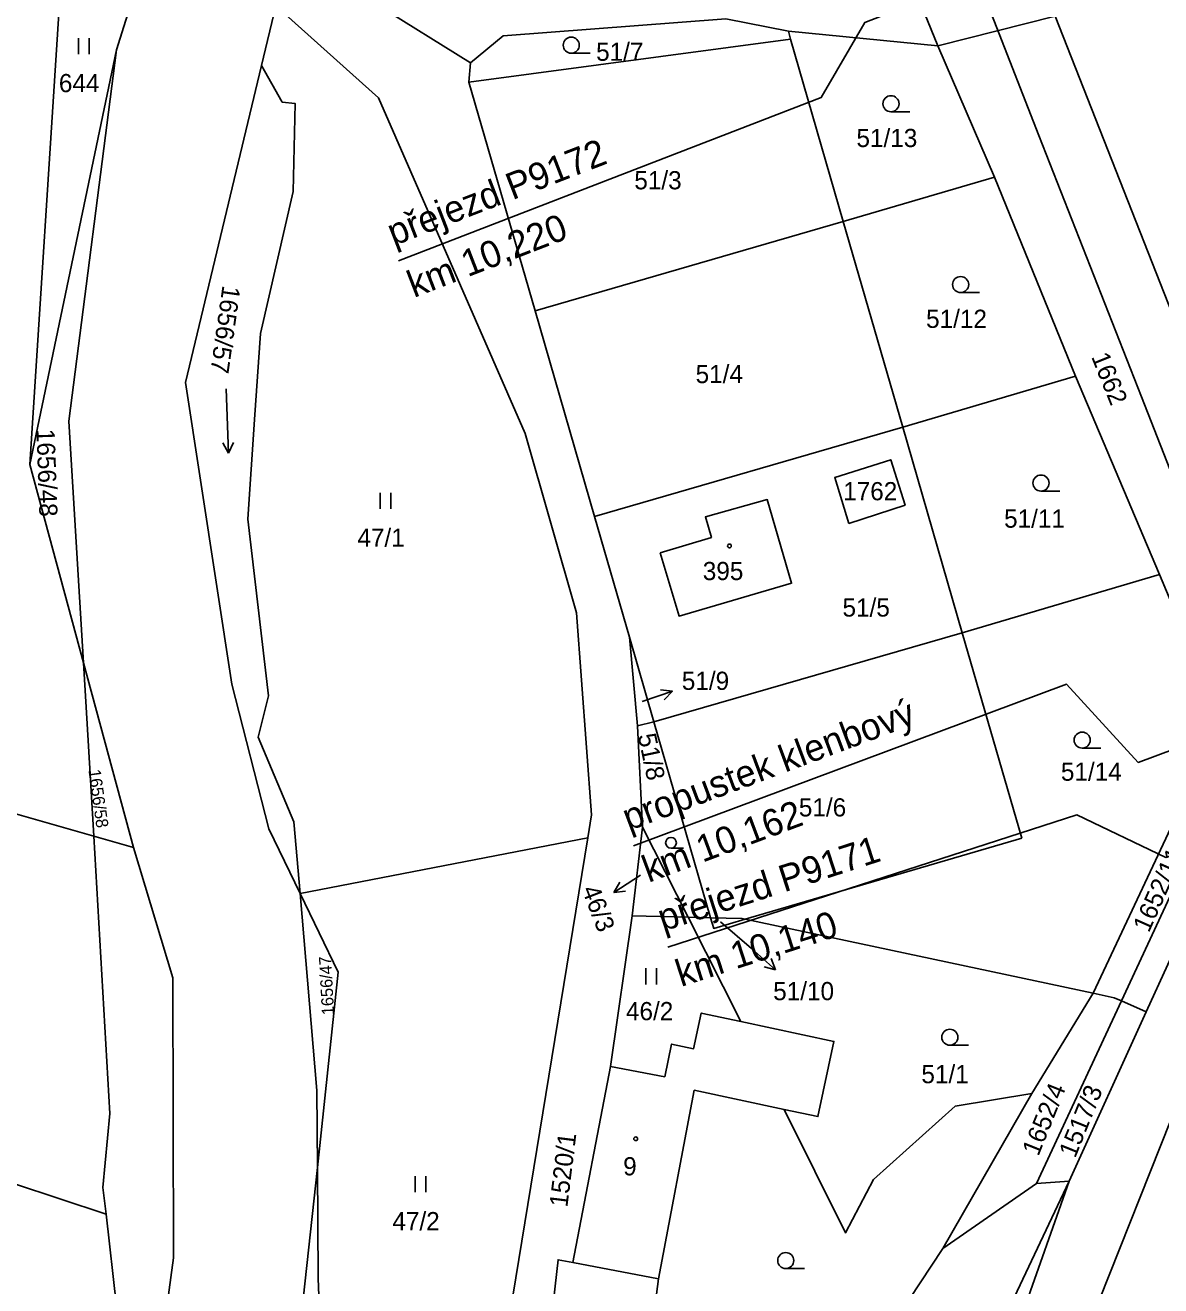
# Model space of a CAD drawing. Extents: x -553916 to -552953, y -1067470 to -1066637.
# Drawn here: x -553633.4 to -553527.3, y -1067025.6 to -1066907.8 of the extents above; entities that cross this region are included whole.
import ezdxf

# ---------------------------------------------------------------- set-up
doc = ezdxf.new("R2010")
doc.units = 0
for name, color, linetype in [('Hranice parcel', 7, 'Continuous'), ('Kolej', 7, 'Continuous'), ('Parcelní čísla', 7, 'Continuous'), ('Pop  PČ popisy', 7, 'Continuous'), ('Propustek', 7, 'Continuous'), ('Přejezd - štěrkové lože', 7, 'Continuous'), ('Vrstva 1', 7, 'Continuous'), ('Značky budov', 7, 'Continuous'), ('Značky kultur', 7, 'Continuous')]:
    doc.layers.add(name, color=color, linetype=linetype)

msp = doc.modelspace()

# ---------------------------------------------------------------- linework, layer by layer
at = {"layer": 'Hranice parcel'}
for p, q in [((-553624.88, -1066910.1), (-553621.57, -1066899.49)), ((-553630.21, -1066905.76), (-553632.98, -1066948.88)), ((-553610.01, -1066906), (-553611.35, -1066911.57)), ((-553591.81, -1066911.32), (-553600.63, -1066905.86)), ((-553591.97, -1066913.14), (-553561.91, -1066909.12)), ((-553562.08, -1066908.37), (-553548.13, -1066909.75)), ((-553561.91, -1066909.12), (-553562.08, -1066908.37)), ((-553561.91, -1066909.12), (-553556.97, -1066926.17)), ((-553632.98, -1066948.88), (-553624.88, -1066910.1)), ((-553611.35, -1066911.57), (-553609.41, -1066915.01)), ((-553591.97, -1066913.14), (-553591.81, -1066911.32)), ((-553585.78, -1066934.51), (-553591.97, -1066913.14)), ((-553542.85, -1066922.01), (-553556.97, -1066926.17)), ((-553585.78, -1066934.51), (-553556.97, -1066926.17)), ((-553556.97, -1066926.17), (-553551.41, -1066945.38)), ((-553580.22, -1066953.72), (-553585.78, -1066934.51)), ((-553535.26, -1066940.6), (-553551.41, -1066945.38)), ((-553580.22, -1066953.72), (-553551.41, -1066945.38)), ((-553551.41, -1066945.38), (-553545.85, -1066964.59)), ((-553632.98, -1066948.88), (-553627.98, -1066967.41)), ((-553576.96, -1066964.99), (-553580.22, -1066953.72)), ((-553545.85, -1066964.59), (-553527.43, -1066959.15)), ((-553574.66, -1066972.93), (-553545.85, -1066964.59)), ((-553545.85, -1066964.59), (-553540.29, -1066983.8)), ((-553576.19, -1066973.29), (-553576.96, -1066964.99)), ((-553574.66, -1066972.93), (-553576.96, -1066964.99)), ((-553627.98, -1066967.41), (-553623.32, -1066984.67)), ((-553574.66, -1066972.93), (-553576.19, -1066973.29)), ((-553575.72, -1066982.77), (-553576.19, -1066973.29)), ((-553569.37, -1066991.22), (-553574.66, -1066972.93)), ((-553520.52, -1066976.45), (-553530.98, -1066998.99)), ((-553519.4, -1066979.7), (-553528.66, -1067000.03)), ((-553608.31, -1066982.27), (-553607.74, -1066988.95)), ((-553576.7, -1066991.04), (-553575.72, -1066982.77)), ((-553571.48, -1066991.17), (-553575.72, -1066982.77)), ((-553627.02, -1066983.6), (-553623.32, -1066984.67)), ((-553625.53, -1067009.52), (-553627.02, -1066983.6)), ((-553607.74, -1066988.95), (-553580.85, -1066983.77)), ((-553589.31, -1067035.5), (-553580.85, -1066983.77)), ((-553540.29, -1066983.8), (-553566.13, -1066991.36)), ((-553576.7, -1066991.04), (-553578.74, -1067005.13)), ((-553571.48, -1066991.17), (-553576.7, -1066991.04)), ((-553566.55, -1067000.93), (-553571.48, -1066991.17)), ((-553569.37, -1066991.22), (-553571.48, -1066991.17)), ((-553533.63, -1066998.28), (-553566.13, -1066991.36)), ((-553539.34, -1067007.65), (-553533.63, -1066998.28)), ((-553530.98, -1066998.99), (-553538.9, -1067016.05)), ((-553528.66, -1067000.03), (-553530.98, -1066998.99)), ((-553535.85, -1067015.85), (-553528.66, -1067000.03)), ((-553578.74, -1067005.13), (-553582.25, -1067023.44)), ((-553547.68, -1067022.12), (-553539.34, -1067007.65)), ((-553626.16, -1067016.42), (-553625.53, -1067009.52)), ((-553608.97, -1067041.18), (-553606.12, -1067014.56)), ((-553606.12, -1067014.56), (-553606.05, -1067024.93)), ((-553625.87, -1067018.94), (-553626.16, -1067016.42)), ((-553555.44, -1067071.33), (-553535.85, -1067015.85)), ((-553538.9, -1067016.05), (-553547.68, -1067022.12)), ((-553535.85, -1067015.85), (-553538.9, -1067016.05)), ((-553582.25, -1067023.44), (-553574.24, -1067024.96)), ((-553575.44, -1067034.44), (-553574.24, -1067024.96))]:
    msp.add_line(p, q, dxfattribs=at)
for points in [[(-553580.85, -1066983.77), (-553580.5, -1066981.61), (-553581.9, -1066962.72), (-553586.71, -1066945.98), (-553600.4, -1066914.59), (-553610.01, -1066906)], [(-553562.08, -1066908.37), (-553567.96, -1066907.21), (-553588.75, -1066908.8), (-553591.81, -1066911.32)], [(-553624.88, -1066910.1), (-553629.34, -1066944.82), (-553627.98, -1066967.41)], [(-553607.74, -1066988.95), (-553610.66, -1066982.93), (-553614.12, -1066969.38), (-553618.45, -1066941.2), (-553611.35, -1066911.57)], [(-553609.41, -1066915.01), (-553608.19, -1066915.13), (-553608.39, -1066923.35), (-553611.45, -1066936.62), (-553612.01, -1066944.65), (-553612.63, -1066953.99), (-553610.68, -1066970.5), (-553611.66, -1066974.34), (-553608.31, -1066982.27)], [(-553556.45, -1066954.37), (-553557.77, -1066950.08), (-553552.53, -1066948.42), (-553551.19, -1066952.66), (-553556.45, -1066954.37)], [(-553574.08, -1066957.11), (-553569.3, -1066955.7), (-553569.85, -1066953.76), (-553564.08, -1066952.14), (-553561.8, -1066959.96), (-553572.32, -1066963.04), (-553574.08, -1066957.11)], [(-553627.98, -1066967.41), (-553627.54, -1066974.67), (-553627.02, -1066983.6)], [(-553533.63, -1066998.28), (-553526.12, -1066982.3), (-553521.68, -1066973.05)], [(-553627.02, -1066983.6), (-553635.52, -1066981.16), (-553652.47, -1067024.37)], [(-553623.32, -1066984.67), (-553619.63, -1066996.83), (-553619.56, -1067023.02), (-553621.7, -1067038.64), (-553627.75, -1067062.69), (-553642.34, -1067082.27), (-553644.52, -1067088.87), (-553655.73, -1067178.24), (-553657.73, -1067185.13), (-553660.17, -1067189.87)], [(-553606.12, -1067014.56), (-553606.17, -1067007.38), (-553607.74, -1066988.95)], [(-553607.74, -1066988.95), (-553604.17, -1066996.31), (-553606.12, -1067014.56)], [(-553569.37, -1066991.22), (-553566.45, -1066991.29), (-553566.13, -1066991.36)], [(-553566.13, -1066991.36), (-553569.08, -1066992.22), (-553569.37, -1066991.22)], [(-553515.43, -1066991.08), (-553526.38, -1067010.19), (-553539.65, -1067043.59), (-553548.33, -1067069.03)], [(-553530.98, -1066998.99), (-553531.64, -1066998.7), (-553533.63, -1066998.28)], [(-553566.55, -1067000.93), (-553570.25, -1067000.14), (-553570.96, -1067003.47), (-553573.01, -1067003.03), (-553573.66, -1067006.09), (-553578.74, -1067005.13)], [(-553562.48, -1067009.13), (-553559.34, -1067009.8), (-553557.85, -1067002.78), (-553566.55, -1067000.93)], [(-553574.24, -1067024.96), (-553570.9, -1067007.35), (-553562.48, -1067009.13)], [(-553539.34, -1067007.65), (-553546.5, -1067008.84), (-553554.13, -1067015.7), (-553556.77, -1067020.68), (-553562.48, -1067009.13)], [(-553648.45, -1067052.9), (-553643.22, -1067013.2), (-553625.87, -1067018.94)], [(-553547.23, -1067042.51), (-553544.77, -1067034.69), (-553535.85, -1067015.85)], [(-553635.52, -1067058.6), (-553624.9, -1067027.54), (-553625.87, -1067018.94)], [(-553547.68, -1067022.12), (-553553.91, -1067031.58), (-553557.59, -1067038.38)], [(-553582.25, -1067023.44), (-553583.62, -1067023.18), (-553585.14, -1067036.63)], [(-553606.05, -1067024.93), (-553605.71, -1067033.75), (-553606.25, -1067040.6)]]:
    msp.add_lwpolyline(points, dxfattribs=at)
at = {"layer": 'Kolej'}
msp.add_lwpolyline([(-553503.32, -1067065.81), (-553502.68, -1067054.03), (-553502.76, -1067041.5), (-553503.63, -1067029.06), (-553504.76, -1067019.97), (-553506.18, -1067011.39), (-553508.33, -1067001.39), (-553510.95, -1066991.62), (-553512.92, -1066985.29), (-553515.65, -1066977.35), (-553517.42, -1066972.53), (-553519.16, -1066967.95), (-553522.89, -1066958.38), (-553529.1, -1066942.55), (-553538.69, -1066918.11), (-553542.91, -1066907.33), (-553546.69, -1066897.68), (-553555.03, -1066876.44), (-553564.64, -1066851.89), (-553574.24, -1066827.43), (-553583.19, -1066804.62)], dxfattribs=at)
at = {"layer": 'Pop  PČ popisy'}
for p, q in [((-553575.77, -1066971.03), (-553572.93, -1066970.05)), ((-553572.93, -1066970.05), (-553574.04, -1066969.91)), ((-553572.93, -1066970.05), (-553573.72, -1066970.85)), ((-553575.91, -1066987.23), (-553578.42, -1066988.88)), ((-553578.42, -1066988.88), (-553577.86, -1066987.91)), ((-553578.42, -1066988.88), (-553577.31, -1066988.75)), ((-553568.43, -1066991.61), (-553565.55, -1066994.11)), ((-553565.55, -1066994.11), (-553563.29, -1066996.08)), ((-553563.29, -1066996.08), (-553563.71, -1066995.04)), ((-553563.29, -1066996.08), (-553564.37, -1066995.8))]:
    msp.add_line(p, q, dxfattribs=at)
at = {"layer": 'Propustek'}
msp.add_lwpolyline([(-553576.56, -1066984.51), (-553536.12, -1066969.4), (-553529.41, -1066976.71), (-553517.54, -1066972.28)], dxfattribs=at)
at = {"layer": 'Přejezd - štěrkové lože'}
for points in [[(-553598.54, -1066929.82), (-553559.03, -1066914.56), (-553554.95, -1066907.55), (-553544.41, -1066903.46)], [(-553573.37, -1066993.96), (-553535.15, -1066981.6), (-553526.82, -1066985.59), (-553514.29, -1066981.32)]]:
    msp.add_lwpolyline(points, dxfattribs=at)
at = {"layer": 'Vrstva 1'}
for p, q in [((-553548.13, -1066909.75), (-553550.91, -1066902.91)), ((-553548.13, -1066909.75), (-553537.18, -1066906.98)), ((-553542.85, -1066922.01), (-553548.13, -1066909.75)), ((-553535.26, -1066940.6), (-553542.85, -1066922.01)), ((-553527.43, -1066959.15), (-553535.26, -1066940.6))]:
    msp.add_line(p, q, dxfattribs=at)
for points in [[(-553537.18, -1066906.98), (-553519.04, -1066953.03), (-553515.05, -1066965.6)], [(-553521.68, -1066973.05), (-553522.23, -1066971.46), (-553527.43, -1066959.15)]]:
    msp.add_lwpolyline(points, dxfattribs=at)
at = {"layer": 'Značky budov'}
for centre in [(-553567.61, -1066956.48), (-553576.37, -1067011.88)]:
    msp.add_circle(centre, 0.175, dxfattribs=at)
at = {"layer": 'Značky kultur'}
for p, q in [((-553628.46, -1066910.52), (-553628.46, -1066909.02)), ((-553627.46, -1066910.52), (-553627.46, -1066909.02)), ((-553582.39, -1066910.43), (-553580.64, -1066910.43)), ((-553552.51, -1066915.9), (-553550.76, -1066915.9)), ((-553546, -1066932.8), (-553544.25, -1066932.8)), ((-553614.63, -1066941.81), (-553614.42, -1066947.81)), ((-553614.42, -1066947.81), (-553614.96, -1066946.85)), ((-553614.42, -1066947.81), (-553613.96, -1066946.81)), ((-553600.24, -1066953), (-553600.24, -1066951.5)), ((-553599.24, -1066953), (-553599.24, -1066951.5)), ((-553538.49, -1066951.35), (-553536.74, -1066951.35)), ((-553534.64, -1066975.37), (-553532.89, -1066975.37)), ((-553573.07, -1066984.72), (-553571.9, -1066984.72)), ((-553575.42, -1066997.45), (-553575.42, -1066995.95)), ((-553574.42, -1066997.45), (-553574.42, -1066995.95)), ((-553547.01, -1067003.14), (-553545.26, -1067003.14)), ((-553596.97, -1067016.88), (-553596.97, -1067015.38)), ((-553595.97, -1067016.88), (-553595.97, -1067015.38)), ((-553562.35, -1067024.01), (-553560.6, -1067024.01))]:
    msp.add_line(p, q, dxfattribs=at)
for centre, radius in [((-553582.39, -1066909.68), 0.75), ((-553552.51, -1066915.15), 0.75), ((-553546, -1066932.05), 0.75), ((-553538.49, -1066950.6), 0.75), ((-553534.64, -1066974.62), 0.75), ((-553573.07, -1066984.22), 0.502), ((-553547.01, -1067002.39), 0.75), ((-553562.35, -1067023.26), 0.75)]:
    msp.add_circle(centre, radius, dxfattribs=at)

# ---------------------------------------------------------------- texts
at = {"layer": 'Parcelní čísla'}
for s, p in [('51/7', (-553580.07, -1066911.14)), ('644', (-553630.28, -1066914.07)), ('51/13', (-553555.74, -1066919.2)), ('51/3', (-553576.5, -1066923.15)), ('51/12', (-553549.23, -1066936.1)), ('51/4', (-553570.77, -1066941.26)), ('1762', (-553556.98, -1066952.21)), ('51/11', (-553541.94, -1066954.77)), ('47/1', (-553602.38, -1066956.55)), ('395', (-553570.1, -1066959.67)), ('51/5', (-553557.04, -1066963.08)), ('51/9', (-553572.06, -1066969.93)), ('51/14', (-553536.63, -1066978.42)), ('51/6', (-553561.12, -1066981.76)), ('51/10', (-553563.52, -1066998.93)), ('46/2', (-553577.28, -1067000.8)), ('51/1', (-553549.67, -1067006.69)), ('9', (-553577.54, -1067015.3)), ('47/2', (-553599.11, -1067020.43))]:
    msp.add_text(s, height=1.7, dxfattribs=at).set_placement(p)
for s, height, rotation, p in [('1656/57', 1.7, 262, (-553614.98, -1066932.08)), ('1656/48', 1.7, 272, (-553632.38, -1066945.56)), ('51/8', 1.7, 282, (-553576.18, -1066974.18)), ('1656/58', 1.14, 278, (-553627.52, -1066977.43)), ('1652/11', 1.7, 66, (-553528.41, -1066992.69)), ('46/3', 1.7, 291, (-553581.43, -1066988.58)), ('1656/47', 1.14, 93, (-553604.55, -1067000.3)), ('1652/4', 1.7, 68, (-553538.74, -1067013.58)), ('1517/3', 1.7, 68, (-553535.3, -1067013.76)), ('1520/1', 1.7, 83, (-553582.76, -1067018.33))]:
    msp.add_text(s, height=height, rotation=rotation, dxfattribs=at).set_placement(p)
at = {"layer": 'Propustek'}
for s, p in [('propustek klenbový', (-553577.03, -1066983.13)), ('km 10,162', (-553575.17, -1066987.97))]:
    msp.add_text(s, height=2.5, rotation=20.4899, dxfattribs=at).set_placement(p)
at = {"layer": 'Přejezd - štěrkové lože'}
for s, rotation, p in [('přejezd P9172', 21.1258, (-553598.99, -1066928.46)), ('km 10,220', 21.1258, (-553597.1, -1066933.31)), ('přejezd P9171', 17.9238, (-553573.82, -1066992.52)), ('km 10,140', 17.9238, (-553572.14, -1066997.7))]:
    msp.add_text(s, height=2.5, rotation=rotation, dxfattribs=at).set_placement(p)
at = {"layer": 'Vrstva 1'}
msp.add_text('1662', height=1.7, rotation=292, dxfattribs=at).set_placement((-553533.82, -1066938.79))

doc.saveas('drawing.dxf')
